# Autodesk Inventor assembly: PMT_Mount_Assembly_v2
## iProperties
Shininess: 64.0
Length Units: 11269
Angle Units: 11279
Time Units: 11290
Mass Units: 11283
Length Display Precision: 3
Angle Display Precision: 2
Compacted: True
Created: 2004-08
Part Number: PMT_Mount_Assembly_v2
Document SubType Name: Assembly
Designer: John Blackburn
Manufacturer: Standard
Standards Organization: Custom
Density: 0.0
Volumn: 0.0
Area: 0.0
PropertySet Name: Model Information
Control State: 0
Master: False
Checked Out: False
Author: John Blackburn
